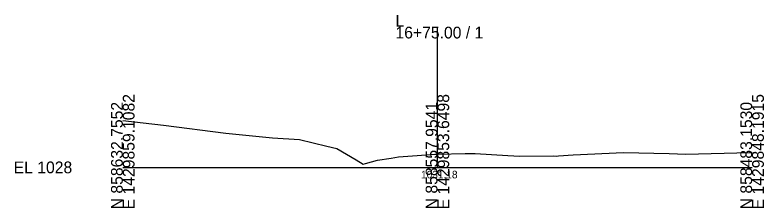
# Model space of a CAD drawing. Extents: x -26 to 176, y -10 to 13058.
# Drawn here: x -25.7 to 152.8, y 10490.3 to 10536.3 of the extents above; entities that cross this region are included whole.
import ezdxf

# ---------------------------------------------------------------- set-up
doc = ezdxf.new("R2010")
doc.units = 0
for name, color, linetype in [('Default', 7, 'Continuous'), ('Exist Cross Section Cell', 7, 'Continuous'), ('Exist XS Center Line Elevation Label', 7, 'Continuous'), ('Exist XS Ground Line', 7, 'Continuous')]:
    doc.layers.add(name, color=color, linetype=linetype)

msp = doc.modelspace()

# ---------------------------------------------------------------- linework, layer by layer
at = {"layer": 'Exist Cross Section Cell'}
for p, q in [((75, 10500), (75, 10533.54)), ((0, 10500), (75, 10500)), ((75, 10500), (150, 10500))]:
    msp.add_line(p, q, dxfattribs=at)
at = {"layer": 'Exist XS Ground Line'}
msp.add_lwpolyline([(0, 10511.18), (9.67, 10510.06), (24.57, 10508.14), (35.71, 10507.08), (42.16, 10506.61), (48.67, 10505.09), (51.01, 10504.53), (55.65, 10501.76), (57.27, 10500.76), (57.85, 10500.9), (60.74, 10501.72), (63.94, 10502.23), (65.68, 10502.51), (70.19, 10502.85), (74.4, 10503.17), (75, 10503.18), (81.61, 10503.29), (83.97, 10503.33), (91.74, 10502.81), (94.62, 10502.7), (102.67, 10502.77), (103.36, 10502.69), (103.88, 10502.77), (107.37, 10503), (119.31, 10503.54), (130.25, 10503.27), (134.22, 10503.17), (149.38, 10503.56), (150, 10503.56)], dxfattribs=at)

# ---------------------------------------------------------------- texts
at = {"layer": 'Default'}
msp.add_text('-', height=0.0001, dxfattribs=at).set_placement((0, 10500))
at = {"layer": 'Exist Cross Section Cell'}
for s, p in [('L', (65, 10533.54)), ('16+75.00 / 1', (65, 10530.74)), ('EL 1028', (-26, 10498.6))]:
    msp.add_text(s, height=2.8, dxfattribs=at).set_placement(p)
for s, p in [('E 1429859.1082', (2.8, 10490)), ('E 1429853.6498', (77.8, 10490)), ('E 1429848.1915', (152.8, 10490)), ('N 858632.7552', (0, 10490)), ('N 858557.9541', (75, 10490)), ('N 858483.1530', (150, 10490))]:
    msp.add_text(s, height=2.8, rotation=90, dxfattribs=at).set_placement(p)
at = {"layer": 'Exist XS Center Line Elevation Label'}
msp.add_text('1031.18', height=1.8, dxfattribs=at).set_placement((71.09, 10497.38))
msp.add_text('1031.18', height=1.8, dxfattribs=at).set_placement((71.09, 10497.38))
msp.add_text('1031.18', height=1.8, dxfattribs=at).set_placement((71.09, 10497.38))

doc.saveas('drawing.dxf')
